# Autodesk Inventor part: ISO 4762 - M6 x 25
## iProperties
Comments: To add or edit properties for Autodesk Inventor files, use iProperties.
Created: 2004-08
Part Number: ISO 4762 - M6 x 25
Vendor: Autodesk Inc.
Document SubType Name: Modeling
Designer: John Blackburn
Material: Default
Description: Hexagon Socket Head Cap Screw
Standard: ISO 4762
Size Designation: M6 x 25
Alert: To add or edit properties for Autodesk Inventor files, use iProperties.
Control State: 0
Master: False
Checked Out: False
Shininess: 64.0
Length Units: 11269
Angle Units: 11279
Time Units: 11290
Mass Units: 11283
Length Display Precision: 3
Angle Display Precision: 2
Compacted: True
EGR: 1
Density: 0.0
Volumn: 0.0
Area: 0.0
PropertySet Name: Model Information
Author: John Blackburn
Revision Number: 8
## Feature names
1. Body [Revolution]
2. Slot [Extrusion]
3. Fillet1
4. Chamfer1
